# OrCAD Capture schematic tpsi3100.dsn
size A
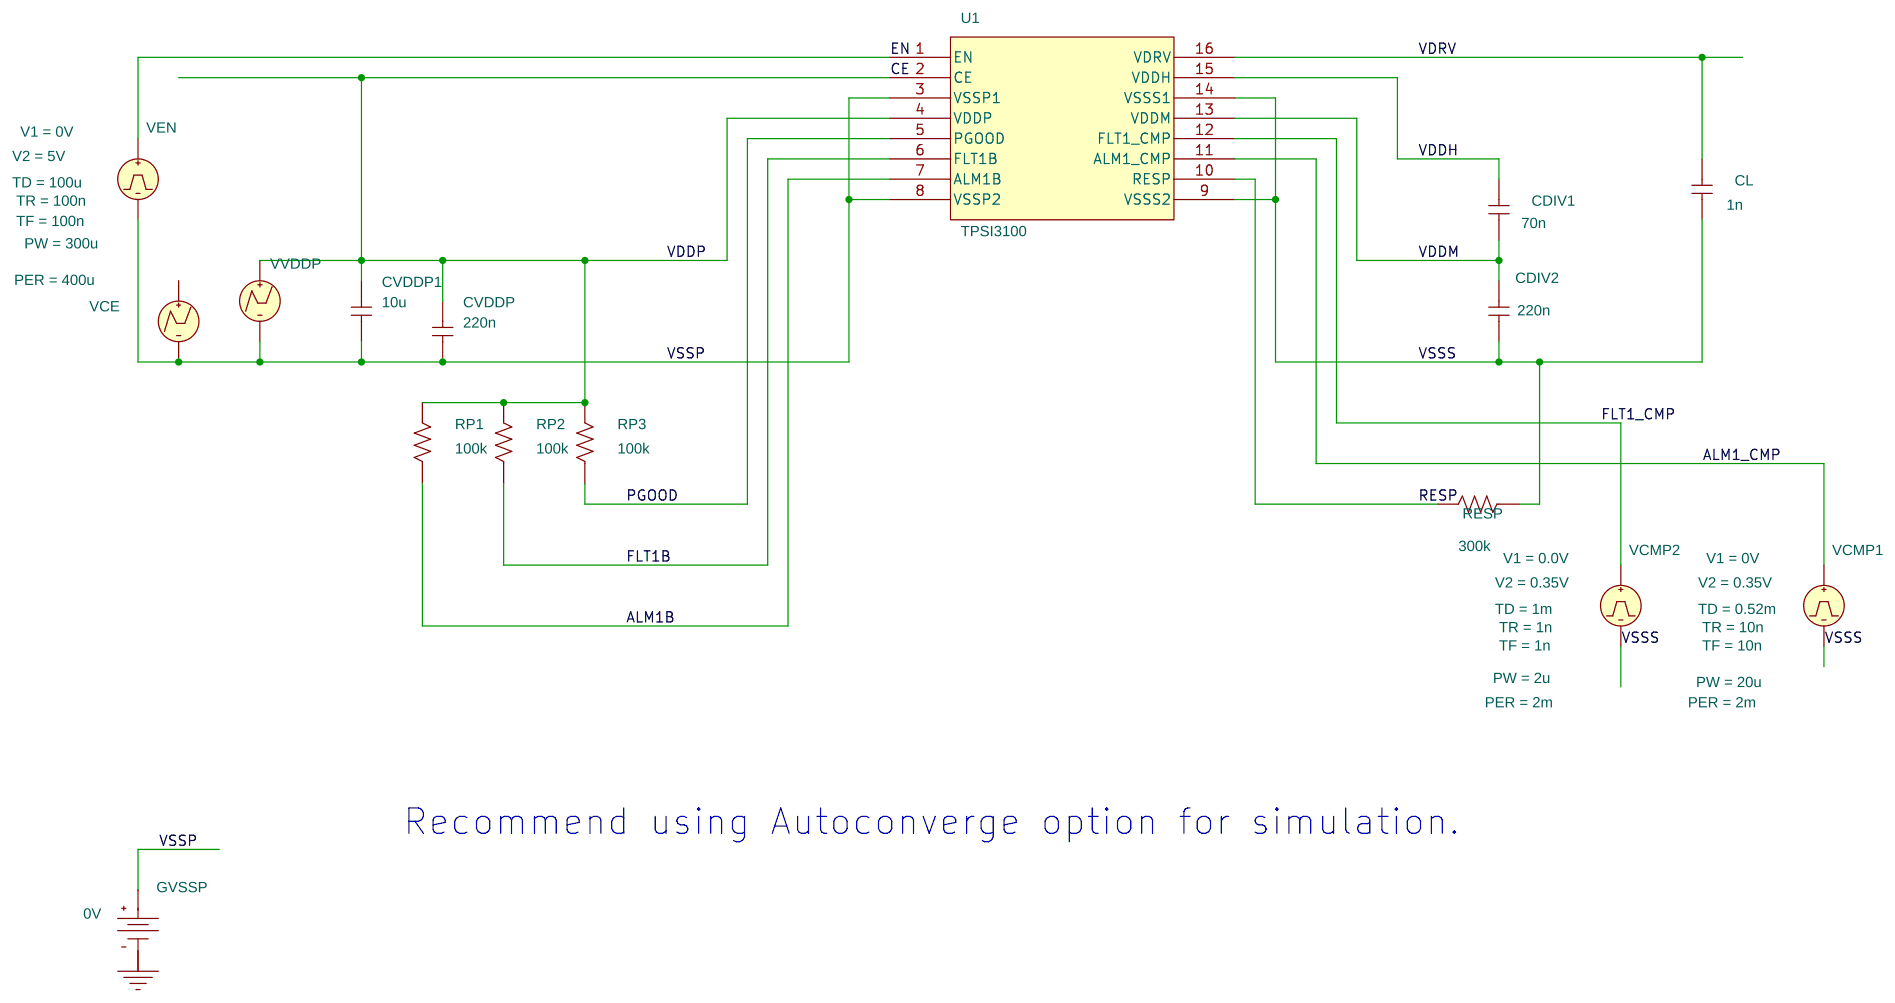
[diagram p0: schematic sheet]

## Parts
CDIV1  70n  [cap196]
CDIV2  220n  [cap196]
CL  1n  [cap196]
CVDDP  220n  [cap196]
CVDDP1  10u  [cap196]
GVSSP  VDC
RESP  300k  [AXRC05]
RP1  100k  [AXRC05]
RP2  100k  [AXRC05]
RP3  100k  [AXRC05]
U1  TPSI3100
VCE  VPWL
VCMP1  VPULSE
VCMP2  VPULSE
VEN  VPULSE
VVDDP  VPWL

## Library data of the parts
CDIV1 CDIV2 CL CVDDP CVDDP1 = C
GVSSP = VDC: DC: 0V
RESP RP1-RP3 = R
U1 = TPSI3100
VCE = VPWL: T1: 0us; T2: 50us; T3: 51us; T4: 950us; T5: 950.1us; T6: 1150us; T7: 5150.05us; V1: 0V; V2: 0V; V3: 5V; V4: 5V; V5: 5V; V6: 5V; V7: 0V
VCMP1 = VPULSE: PER: 2m; PW: 20u; TD: 0.52m; TF: 10n; TR: 10n; V1: 0V; V2: 0.35V
VCMP2 = VPULSE: PER: 2m; PW: 2u; TD: 1m; TF: 1n; TR: 1n; V1: 0.0V; V2: 0.35V
VEN = VPULSE: PER: 400u; PW: 300u; TD: 100u; TF: 100n; TR: 100n; V1: 0V; V2: 5V
VVDDP = VPWL: T1: 0us; T2: 5us; T3: 5.05us; T4: 950us; T5: 960.1us; V1: 0V; V2: 0V; V3: 5V; V4: 5V; V5: 5V

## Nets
VDDH: CDIV1.2 U1.15(VDDH)
VDDM: CDIV1.1 CDIV2.2 U1.13(VDDM)
VSSP: CVDDP.1 CVDDP1.1 GVSSP.0(+) U1.3(VSSP1) U1.8(VSSP2) VCE.2(-) VEN.2(-) VVDDP.2(-)
VSSS: CDIV2.1 CL.1 RESP.1 U1.9(VSSS2) U1.14(VSSS1) VCMP1.2(-) VCMP2.2(-)
0: GVSSP.1(-)
ALM1_CMP: U1.11(ALM1_CMP) VCMP1.1(+)
ALM1B: RP1.1 U1.7(ALM1B)
CE: CVDDP.2 CVDDP1.2 RP1.2 RP2.2 RP3.2 U1.2(CE) U1.4(VDDP) VVDDP.1(+)
EN: U1.1(EN) VEN.1(+)
FLT1_CMP: U1.12(FLT1_CMP) VCMP2.1(+)
FLT1B: RP2.1 U1.6(FLT1B)
PGOOD: RP3.1 U1.5(PGOOD)
RESP: RESP.2 U1.10(RESP)
VDRV: CL.2 U1.16(VDRV)

Not connected (* = marked no-connect by the designer): VCE 1(+)

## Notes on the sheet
- Recommend using Autoconverge option for simulation.
